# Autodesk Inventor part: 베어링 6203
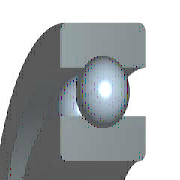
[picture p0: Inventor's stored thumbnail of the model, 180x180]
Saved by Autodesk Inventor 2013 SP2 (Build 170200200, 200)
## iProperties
IsCustomPart: 0
Company: 한국ATC센터
Created: 2015-11
Part Number: 베어링 6203
Material: 강철, 연강
Description: 깊은 그루브 볼 베어링
Document SubType Name: Modeling
Standard: KS B 2023
Designer: mdu
Standards Organization: KS
Language: ko-KR
Size Designation: 6203 - 17 x 40 x 12
Categories: <MemberInstance><Categories><Category DisplayName="샤프트 부품" InternalName="7f7aeb1f-a693-4053-b835-cee3144e0d98" Mnemonic="SHFT"><Category DisplayName="베어링" Inter
Density: 1 g/cm^3
Author: mdu
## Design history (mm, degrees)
sketch "스케치" dims "d0" = 5.98 (= -0.26 x WD + 0.26 x BD)
  geometry: L1 (3.01, 14.25)-(8.99, 14.25); L2 (6, 14.25)-(6, 11.26); L3 (6, 14.25)-(6, 17.24); L4 (3.778, 12.249)-(0, 12.249); L5 (0, 8.5)-(12, 8.5); L6 (3.778, 16.251)-(0, 16.251); L7 (0, 20)-(12, 20); L8 (12, 8.5)-(12, 12.249); L9 (8.222, 12.249)-(12, 12.249); L10 (8.222, 16.251)-(12, 16.251); L11 (12, 20)-(12, 16.251); L12 (-1.4, 0)-(8.4, 0) reference; L13 (0, -0.3)-(0, 5.3) reference
  constraints: 22 end point, 4 point on line, 2 collinear, 2 perpendicular, 2 symmetric about line, 1 midpoint, 1 parallel, 14 other
  dimensions: "d9" = 17 diameter of L5 L12 (= WD); "d11" = 40 diameter of L7 L12 (= BD); "d12" = 12 distance between parallel lines of L8 L13 (= KB); "d13" = 24.498 diameter of L9 L12 (= 0.326 x BD + 0.674 x WD)
revolve "본체" stored, may be unused: angle "d6" = 90 deg
revolve "볼" stored, may be unused: angle "d7" = 90 deg
pattern_circular "IDS_ARRAYBALL[SIMPL:T]" dims angle "d3" = 360 deg
body "Solid1"
fillet "모깎기1" dims "d1" = 0.6 (= KRS)
other parameters: "WD" = 17 [user parameter; used in 5 equation terms], "BD" = 40 [user parameter; used in 5 equation terms], "KB" = 12 [user parameter; used in 1 equation term], "KRS" = 0.6 [user parameter; used in 1 equation term], "d4" = 0, "d5" = 0, "d8" = 0, "d14" = 0, "d15" = 0, "BBA" = 0 [user parameter], "BC0" = 4750000 [user parameter], "BC" = 9560000 [user parameter], "WR" = 8.5 (= 0.5 x WD) [user parameter]
